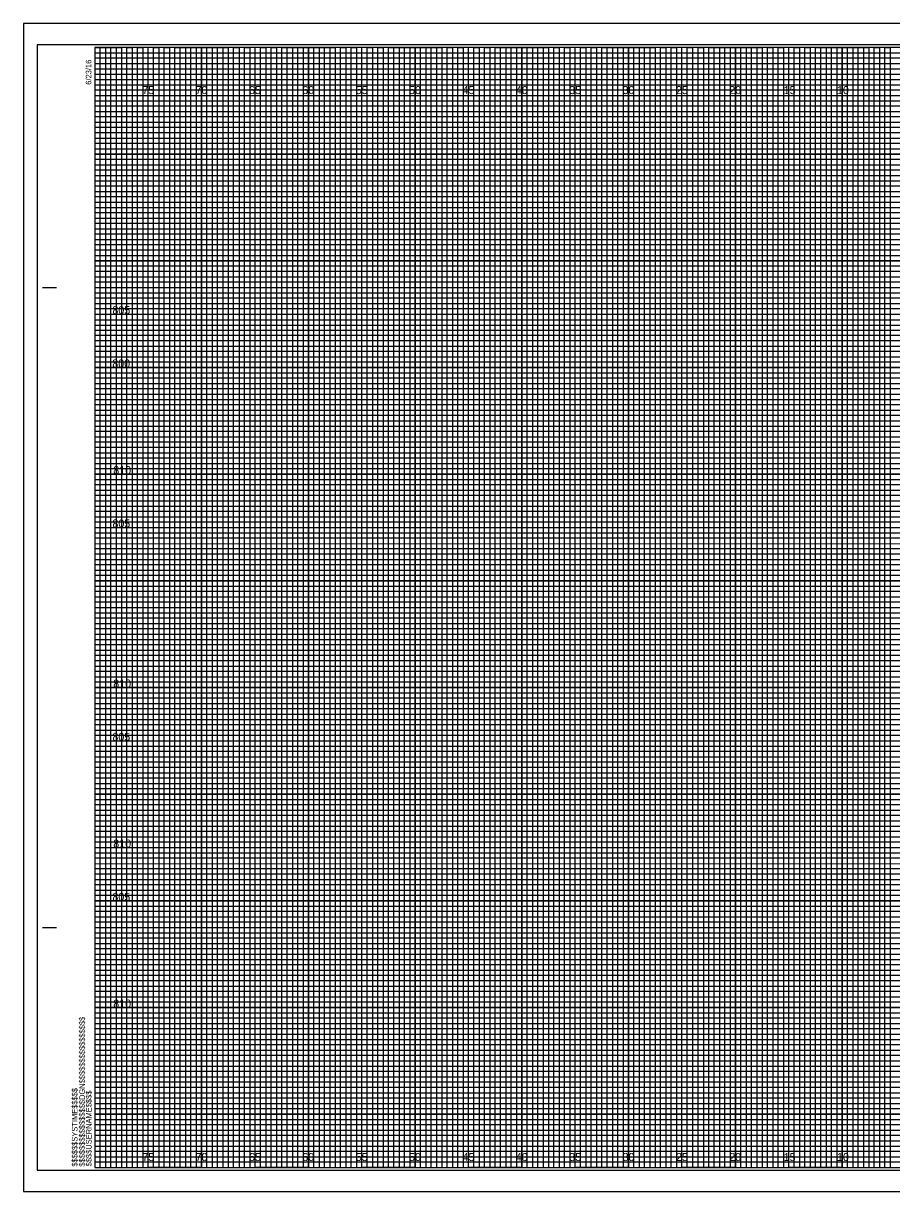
# Model space of a CAD drawing. Extents: x -7 to 162, y -2 to 107.
# Drawn here: x -6.7 to 74.6, y -2.3 to 107.3 of the extents above; entities that cross this region are included whole.
import ezdxf

# ---------------------------------------------------------------- set-up
doc = ezdxf.new("R2010")
doc.units = 0
for name, color, linetype in [('Exist Cross Section Cell', 7, 'Continuous'), ('Exist XS Center Line Elevation Label', 7, 'Continuous'), ('Prop CMT Pvmt Wedge Surface 2', 7, 'Continuous'), ('Prop CMT Pvmt Wedge Surface 3', 7, 'Continuous'), ('Prop XS Elevation Labels', 7, 'Continuous'), ('Prop XS Hydro Elevations', 7, 'Continuous'), ('Prop XS SE Text', 7, 'Continuous'), ('Prop XS Side Slope Text', 7, 'Continuous'), ('Sheet Cross Section Grid Minor 2 CELL', 7, 'Continuous'), ('Sheet Cutting Line CELL', 7, 'Continuous'), ('Sheet DOT Grid CELL', 7, 'Continuous')]:
    doc.layers.add(name, color=color, linetype=linetype)

msp = doc.modelspace()

# ---------------------------------------------------------------- linework, layer by layer
at = {"layer": 'Exist Cross Section Cell'}
for p, q in [((5, 105), (0, 105)), ((5, 0), (5, 105)), ((15, 105), (10, 105)), ((10, 105), (10, 0)), ((15, 0), (15, 105)), ((25, 105), (20, 105)), ((20, 105), (20, 0)), ((25, 0), (25, 105)), ((35, 105), (30, 105)), ((30, 105), (30, 0)), ((35, 0), (35, 105)), ((45, 105), (40, 105)), ((40, 105), (40, 0)), ((45, 0), (45, 105)), ((55, 105), (50, 105)), ((50, 105), (50, 0)), ((55, 0), (55, 105)), ((65, 105), (60, 105)), ((60, 105), (60, 0)), ((65, 0), (65, 105)), ((75, 105), (70, 105)), ((70, 105), (70, 0)), ((10, 0), (5, 0)), ((20, 0), (15, 0)), ((30, 0), (25, 0)), ((40, 0), (35, 0)), ((50, 0), (45, 0)), ((60, 0), (55, 0)), ((70, 0), (65, 0))]:
    msp.add_line(p, q, dxfattribs=at)
for points in [[(0, 100), (160, 100), (160, 95), (0, 95)], [(0, 90), (160, 90), (160, 85), (0, 85)], [(0, 80), (160, 80), (160, 75), (0, 75)], [(0, 70), (160, 70), (160, 65), (0, 65)], [(0, 60), (160, 60), (160, 55), (0, 55)], [(0, 50), (160, 50), (160, 45), (0, 45)], [(0, 40), (160, 40), (160, 35), (0, 35)], [(0, 30), (160, 30), (160, 25), (0, 25)], [(0, 20), (160, 20), (160, 15), (0, 15)], [(0, 10), (160, 10), (160, 5), (0, 5)]]:
    msp.add_lwpolyline(points, dxfattribs=at)
at = {"layer": 'Exist XS Center Line Elevation Label'}
for points in [[(0, 105), (2.5, 105), (2.5, 0), (7.5, 0), (7.5, 105), (12.5, 105), (12.5, 0), (17.5, 0), (17.5, 105), (22.5, 105), (22.5, 0), (27.5, 0), (27.5, 105), (32.5, 105), (32.5, 0), (37.5, 0), (37.5, 105), (42.5, 105), (42.5, 0), (47.5, 0), (47.5, 105), (52.5, 105), (52.5, 0), (57.5, 0), (57.5, 105), (62.5, 105), (62.5, 0), (67.5, 0), (67.5, 105), (72.5, 105), (72.5, 0), (77.5, 0)], [(0, 102.5), (137.5, 102.5)], [(0, 92.5), (160, 92.5), (160, 97.5), (0, 97.5)], [(0, 82.5), (160, 82.5), (160, 87.5), (0, 87.5)], [(0, 72.5), (160, 72.5), (160, 77.5), (0, 77.5)], [(0, 62.5), (160, 62.5), (160, 67.5), (0, 67.5)], [(0, 52.5), (160, 52.5), (160, 57.5), (0, 57.5)], [(0, 42.5), (160, 42.5), (160, 47.5), (0, 47.5)], [(0, 32.5), (160, 32.5), (160, 37.5), (0, 37.5)], [(0, 22.5), (160, 22.5), (160, 27.5), (0, 27.5)], [(0, 12.5), (160, 12.5), (160, 17.5), (0, 17.5)], [(0, 2.5), (160, 2.5), (160, 7.5), (0, 7.5)]]:
    msp.add_lwpolyline(points, dxfattribs=at)
at = {"layer": 'Prop CMT Pvmt Wedge Surface 2'}
msp.add_lwpolyline([(-6.7, -2.25), (161.65, -2.25), (161.65, 107.25), (-6.7, 107.25)], close=True, dxfattribs=at)
at = {"layer": 'Prop CMT Pvmt Wedge Surface 3'}
msp.add_lwpolyline([(-5.4, -0.25), (161.2, -0.25), (161.2, 105.25), (-5.4, 105.25)], close=True, dxfattribs=at)
at = {"layer": 'Prop XS Hydro Elevations'}
for p, q in [((-4.9, 82.5), (-3.65, 82.5)), ((-4.85, 82.5), (-3.6, 82.5)), ((-4.9, 22.5), (-3.65, 22.5)), ((-4.85, 22.5), (-3.6, 22.5)), ((0, 0), (0, 0)), ((0, 0), (0, 0)), ((0, 0), (0, 0)), ((0, 0), (0, 0)), ((0, 0), (0, 0)), ((0, 0), (0, 0)), ((0, 0), (0, 0))]:
    msp.add_line(p, q, dxfattribs=at)
msp.add_lwpolyline([(160, 105), (0, 105), (0, 0), (160, 0)], close=True, dxfattribs=at)
at = {"layer": 'Prop XS Side Slope Text'}
for p, q in [((0, 104.5), (130, 104.5)), ((130, 103.99), (0, 103.99)), ((0, 103.99), (0, 103.5)), ((0, 103.5), (130, 103.5)), ((130, 102.95), (0, 102.95)), ((0, 102.95), (0, 102)), ((0, 102), (160, 102))]:
    msp.add_line(p, q, dxfattribs=at)
for points in [[(0, 101.5), (135, 101.5), (160, 101.5), (160, 101), (0, 101)], [(0, 100.5), (160, 100.5), (160, 99.5), (0, 99.5)], [(0, 99), (160, 99), (160, 98.5), (0, 98.49)], [(0, 98), (160, 98), (160, 97), (0, 97)], [(0, 96.5), (160, 96.5), (160, 96), (0, 96)], [(0, 95.5), (160, 95.5), (160, 94.5), (0, 94.5)], [(0, 94), (160, 94), (160, 93.5), (0, 93.5)], [(0, 93), (160, 93), (160, 92), (0, 92)], [(0, 91.5), (160, 91.5), (160, 91), (0, 91)], [(0, 90.5), (160, 90.5), (160, 89.5), (0, 89.5)], [(0, 89), (160, 89), (160, 88.5), (0, 88.5)], [(0, 88), (160, 88), (160, 86.98), (160, 86.5), (160, 86), (0, 86)], [(0, 87), (160, 87), (160, 86.5), (0, 86.5)], [(0, 85.5), (160, 85.5), (160, 84.5), (0, 84.52)], [(0, 84.52), (160, 84.5), (160, 84), (0, 84)], [(0, 83.5), (160, 83.5), (160, 83), (0, 83)], [(0, 82), (160, 82), (160, 81.5), (0, 81.5)], [(0, 81), (160, 81), (160, 80.5), (0, 80.5)], [(-0.04, 79.45), (160, 79.45), (160, 78.94), (-0.04, 78.94)], [(0, 78.5), (160, 78.5), (160, 78), (0, 78)], [(0, 77), (160, 77), (160, 76.5), (0, 76.5)], [(0, 76), (160, 76), (160, 75.5), (0, 75.5)], [(0, 74.5), (160, 74.5), (160, 74), (0, 74)], [(0, 73.5), (160, 73.5), (160, 73), (0, 73)], [(0, 72), (160, 72), (160, 71.5), (0, 71.5)], [(0, 71), (160, 71), (160, 70.5), (0, 70.5)], [(0, 69.5), (160, 69.5), (160, 68.99), (0, 69)], [(0, 68.5), (160, 68.5), (160, 68), (0, 68)], [(0, 67), (160, 67), (160, 66.5), (0, 66.5)], [(0, 66), (160, 66), (160, 65.5), (0, 65.5)], [(0, 64.5), (160, 64.5), (160, 64), (0, 64)], [(0, 63.5), (160, 63.5), (160, 63), (0, 63)], [(0, 62), (160, 62), (160, 61.5), (0, 61.5)], [(0, 61), (160, 61), (160, 60.5), (0, 60.5)], [(0, 59.5), (160, 59.5), (160, 59), (0, 59)], [(0, 58.5), (160.03, 58.45), (160, 58), (0, 58)], [(0, 57), (160, 57), (160, 56.5), (0, 56.5)], [(0, 56), (160, 56), (160, 55.5), (0, 55.5)], [(0, 54.5), (160, 54.5), (160, 54), (0, 54)], [(0, 53.5), (160, 53.5), (160, 53), (0, 53)], [(0, 52), (160, 52), (160, 51.5), (0, 51.5)], [(0, 51), (160, 51), (160, 50.5), (0, 50.5)], [(0, 49.5), (160, 49.5), (160, 49), (0, 49)], [(0, 48.5), (160, 48.5), (160, 48), (0, 48)], [(0, 47), (160, 47), (160, 46.5), (0, 46.5)], [(0, 46), (160, 46), (160, 45.5), (0, 45.5)], [(0, 44.5), (160, 44.5), (160, 44), (0, 44)], [(0, 43.5), (160, 43.5), (160, 43), (0, 43)], [(0, 42), (160, 42), (160, 41.5), (0, 41.5)], [(0, 41), (160, 41), (160, 40.5), (0, 40.5)], [(0, 39.5), (160, 39.5), (160, 38.99), (0, 39)], [(0, 38.5), (160, 38.5), (160, 38), (0, 38)], [(0, 37), (160, 37), (160, 36.5), (0, 36.5)], [(0, 36), (160, 36), (160, 35.5), (0, 35.5)], [(0, 34.5), (160, 34.5), (160, 34), (0, 34)], [(0, 33.5), (160, 33.5), (160, 33), (0, 33)], [(0, 32), (160, 32), (160, 31.5), (0, 31.5)], [(0, 31), (160, 31), (160, 30.5), (0, 30.5)], [(0, 29.5), (160, 29.5), (160, 29), (0, 29)], [(0, 28.5), (160.03, 28.46), (160, 28), (0, 28)], [(0, 27), (160, 27), (160, 26.5), (0, 26.5)], [(0, 26), (160, 26), (160, 25.5), (0, 25.5)], [(0, 24.5), (160, 24.5), (160, 24), (0, 24)], [(0, 23.5), (160, 23.5), (160, 23), (0, 23)], [(0, 22), (160, 22), (160, 21.5), (0, 21.5)], [(0, 21), (160, 21), (160, 20.5), (0, 20.5)], [(0, 19.5), (160, 19.5), (160, 19), (0, 19)], [(0, 18.5), (160, 18.5), (160, 18), (0, 18)], [(0, 17), (160, 17), (160, 16.5), (0, 16.5)], [(0, 16), (160, 16), (160, 15.5), (0, 15.5)], [(0, 14.5), (160, 14.5), (160, 14), (0, 14)], [(0, 13.5), (160, 13.5), (160, 13), (0, 13)], [(0, 12), (160, 12), (160, 11.5), (0, 11.5)], [(0, 11), (160, 11), (160, 10.5), (0, 10.5)], [(0, 9.5), (160, 9.5), (160, 9), (0, 9)], [(0, 8.5), (160, 8.5), (160, 8), (0, 8)], [(0, 7), (160, 7), (160, 6.5), (0, 6.5)], [(0, 6), (160, 6), (160, 5.5), (0, 5.5)], [(0, 4.5), (160, 4.5), (160, 4), (0, 4)], [(0, 3.5), (160, 3.5), (160, 3), (0, 3)], [(0, 2), (160, 2), (160, 1.5), (0, 1.5)], [(0, 1), (160, 1), (160, 0.5), (0, 0.5)]]:
    msp.add_lwpolyline(points, dxfattribs=at)
at = {"layer": 'Sheet Cross Section Grid Minor 2 CELL'}
for points in [[(0, 0), (0.5, 0), (0.5, 105), (1, 105), (1, 0)], [(1, 0), (1.5, 0), (1.5, 105), (2, 105), (2, 0)], [(2.5, 0), (3, 0), (3, 105), (3.5, 105), (3.5, 0)], [(3.5, 0), (4, 0), (4, 105), (4.5, 105), (4.5, 0)], [(5, 0), (5.5, 0), (5.5, 105), (6, 105), (6, 0)], [(6, 0), (6.5, 0), (6.5, 105), (7, 105), (7, 0)], [(7.5, 0), (8, 0), (8, 105), (8.5, 105), (8.5, 0)], [(8.5, 0), (9, 0), (9, 105), (9.5, 105), (9.5, 0)], [(10, 0), (10.5, 0), (10.5, 105), (11, 105), (11, 0)], [(11, 0), (11.5, 0), (11.5, 105), (12, 105), (12, 0)], [(12.5, 0), (13, 0), (13, 105), (13.5, 105), (13.5, 0)], [(13.5, 0), (14, 0), (14, 105), (14.5, 105), (14.5, 0)], [(15, 0), (15.5, 0), (15.5, 105), (16, 105), (16, 0)], [(16, 0), (16.5, 0), (16.5, 105), (17, 105), (17, 0)], [(17.5, 0), (18, 0), (18, 105), (18.5, 105), (18.5, 0)], [(18.5, 0), (19, 0), (19, 105), (19.5, 105), (19.5, 0)], [(20, 0), (20.5, 0), (20.5, 105), (21, 105), (21, 0)], [(21, 0), (21.5, 0), (21.5, 105), (22, 105), (22, 0)], [(22.5, 0), (23, 0), (23, 105), (23.5, 105), (23.5, 0)], [(23.5, 0), (24, 0), (24, 105), (24.5, 105), (24.5, 0)], [(25, 0), (25.5, 0), (25.5, 105), (26, 105), (26, 0)], [(26, 0), (26.5, 0), (26.5, 105), (27, 105), (27, 0)], [(27.5, 0), (28, 0), (28, 105), (28.5, 105), (28.5, 0)], [(28.5, 0), (29, 0), (29, 105), (29.5, 105), (29.5, 0)], [(30, 0), (30.5, 0), (30.5, 105), (31, 105), (31, 0)], [(31, 0), (31.5, 0), (31.5, 105), (32, 105), (32, 0)], [(32.5, 0), (33, 0), (33, 105), (33.5, 105), (33.5, 0)], [(33.5, 0), (34, 0), (34, 105), (34.5, 105), (34.5, 0)], [(35, 0), (35.5, 0), (35.5, 105), (36, 105), (36, 0)], [(36, 0), (36.5, 0), (36.5, 105), (37, 105), (37, 0)], [(37.5, 0), (38, 0), (38, 105), (38.5, 105), (38.5, 0)], [(38.5, 0), (39, 0), (39, 105), (39.5, 105), (39.5, 0)], [(40, 0), (40.5, 0), (40.5, 105), (41, 105), (41, 0)], [(41, 0), (41.5, 0), (41.5, 105), (42, 105), (42, 0)], [(42.5, 0), (43, 0), (43, 105), (43.5, 105), (43.5, 0)], [(43.5, 0), (44, 0), (44, 105), (44.5, 105), (44.5, 0)], [(45, 0), (45.5, 0), (45.5, 105), (46, 105), (46, 0)], [(46, 0), (46.5, 0), (46.5, 105), (47, 105), (47, 0)], [(47.5, 0), (48, 0), (48, 105), (48.5, 105), (48.5, 0)], [(48.5, 0), (49, 0), (49, 105), (49.5, 105), (49.5, 0)], [(50, 0), (50.5, 0), (50.5, 105), (51, 105), (51, 0)], [(51, 0), (51.5, 0), (51.5, 105), (52, 105), (52, 0)], [(52.5, 0), (53, 0), (53, 105), (53.5, 105), (53.5, 0)], [(53.5, 0), (54, 0), (54, 105), (54.5, 105), (54.5, 0)], [(55, 0), (55.5, 0), (55.5, 105), (56, 105), (56, 0)], [(56, 0), (56.5, 0), (56.5, 105), (57, 105), (57, 0)], [(57.5, 0), (58, 0), (58, 105), (58.5, 105), (58.5, 0)], [(58.5, 0), (59, 0), (59, 105), (59.5, 105), (59.5, 0)], [(60, 0), (60.5, 0), (60.5, 105), (61, 105), (61, 0)], [(61, 0), (61.5, 0), (61.5, 105), (62, 105), (62, 0)], [(62.5, 0), (63, 0), (63, 105), (63.5, 105), (63.5, 0)], [(63.5, 0), (64, 0), (64, 105), (64.5, 105), (64.5, 0)], [(65, 0), (65.5, 0), (65.5, 105), (66, 105), (66, 0)], [(66, 0), (66.5, 0), (66.5, 105), (67, 105), (67, 0)], [(67.5, 0), (68, 0), (68, 105), (68.5, 105), (68.5, 0)], [(68.5, 0), (69, 0), (69, 105), (69.5, 105), (69.5, 0)], [(70, 0), (70.5, 0), (70.5, 105), (71, 105), (71, 0)], [(71, 0), (71.5, 0), (71.5, 105), (72, 105), (72, 0)], [(72.5, 0), (73, 0), (73, 105), (73.5, 105), (73.5, 0)], [(73.5, 0), (74, 0), (74, 105), (74.5, 105), (74.5, 0)]]:
    msp.add_lwpolyline(points, dxfattribs=at)
at = {"layer": 'Sheet Cutting Line CELL'}
for p, q in [((161.65, 107.25), (-6.7, 107.25)), ((-6.7, 107.25), (-6.7, -2.25)), ((-6.7, -2.25), (161.65, -2.25))]:
    msp.add_line(p, q, dxfattribs=at)
at = {"layer": 'Sheet DOT Grid CELL'}
for p, q in [((5, 0), (5, 105)), ((10, 0), (10, 105)), ((15, 0), (15, 105)), ((20, 0), (20, 105)), ((25, 0), (25, 105)), ((30, 0), (30, 105)), ((35, 0), (35, 105)), ((40, 0), (40, 105)), ((45, 0), (45, 105)), ((50, 0), (50, 105)), ((55, 0), (55, 105)), ((60, 0), (60, 105)), ((65, 0), (65, 105)), ((70, 0), (70, 105)), ((0, 100), (160, 100)), ((0, 95), (160, 95)), ((0, 90), (160, 90)), ((0, 85), (160, 85)), ((0, 80), (160, 80)), ((0, 75), (160, 75)), ((0, 70), (160, 70)), ((0, 65), (160, 65)), ((0, 60), (160, 60)), ((0, 55), (160, 55)), ((0, 50), (160, 50)), ((0, 45), (160, 45)), ((0, 40), (160, 40)), ((0, 35), (160, 35)), ((0, 30), (160, 30)), ((0, 25), (160, 25)), ((0, 20), (160, 20)), ((0, 15), (160, 15)), ((0, 10), (160, 10)), ((0, 5), (160, 5))]:
    msp.add_line(p, q, dxfattribs=at)

# ---------------------------------------------------------------- texts
at = {"layer": 'Prop XS Elevation Labels'}
for s, p in [('805', (1.64, 80)), ('800', (1.63, 75)), ('810', (1.72, 65)), ('805', (1.64, 60)), ('810', (1.72, 45)), ('805', (1.64, 40)), ('810', (1.72, 30)), ('805', (1.64, 25)), ('810', (1.72, 15))]:
    msp.add_text(s, height=0.75, dxfattribs=at).set_placement(p)
at = {"layer": 'Prop XS Hydro Elevations'}
for s, p in [('6/23/16', (-0.33, 101.5)), ('$$$$$$$$$$$$$$$$DGN$$$$$$$$$$$$$$$$', (-0.94, 0.09)), ('$$$$$$SYSTIME$$$$$', (-1.63, 0.09)), ('$$$$USERNAME$$$$', (-0.31, 0.12))]:
    msp.add_text(s, height=0.525, rotation=90, dxfattribs=at).set_placement(p)
at = {"layer": 'Prop XS SE Text'}
for s, p in [('75', (4.44, 100.62)), ('70', (9.43, 100.62)), ('65', (14.44, 100.62)), ('60', (19.43, 100.62)), ('55', (24.44, 100.62)), ('50', (29.43, 100.62)), ('45', (34.44, 100.62)), ('40', (39.43, 100.62)), ('35', (44.44, 100.62)), ('30', (49.43, 100.62)), ('25', (54.44, 100.62)), ('20', (59.43, 100.62)), ('15', (64.53, 100.62)), ('10', (69.52, 100.62)), ('75', (4.44, 0.62)), ('70', (9.43, 0.62)), ('65', (14.44, 0.62)), ('60', (19.43, 0.62)), ('55', (24.44, 0.62)), ('50', (29.43, 0.62)), ('45', (34.44, 0.62)), ('40', (39.43, 0.62)), ('35', (44.44, 0.62)), ('30', (49.43, 0.62)), ('25', (54.44, 0.62)), ('20', (59.43, 0.62)), ('15', (64.53, 0.62)), ('10', (69.52, 0.62))]:
    msp.add_text(s, height=0.75, dxfattribs=at).set_placement(p)

doc.saveas('drawing.dxf')
